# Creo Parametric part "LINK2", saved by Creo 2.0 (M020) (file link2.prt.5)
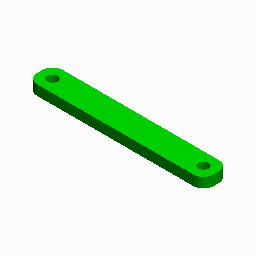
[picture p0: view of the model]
Units: Inch lbm Second (Pro/E Default); INCH, POUND, SECS

Created from: INLBS_PART_SOLID.PRT

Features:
  1. datum plane "RIGHT"
  2. datum plane "TOP"
  3. datum plane "FRONT"
  4. coordinate system
  5. sketch "Sketch 1"
  6. extrusion "Extrude 1", "Sketch 1"
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
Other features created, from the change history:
  datum plane "DTM1"
  datum plane "BOTTON"
  round "Round 1"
